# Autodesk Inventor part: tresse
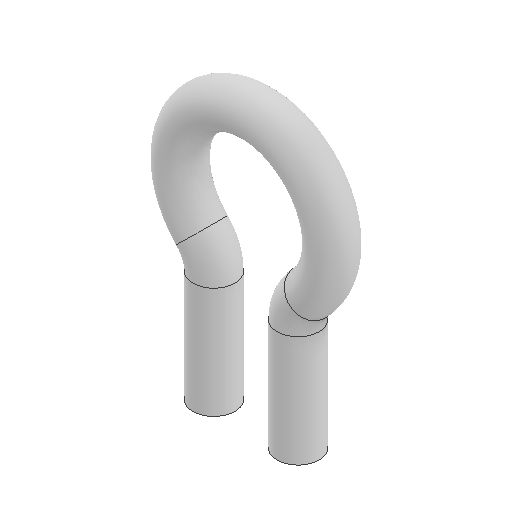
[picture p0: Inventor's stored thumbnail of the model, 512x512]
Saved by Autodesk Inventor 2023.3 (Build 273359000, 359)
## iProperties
Created: 2024-11
Part Number: tresse
Material: Générique
Description: STEP AP203
Document SubType Name: Modeling
Designer: Thier
Density: 1 g/cm^3
Appearance: Par défaut
Sending System: SolidWorks 2017
Preprocessor: SwSTEP 2.0
Title: tresse.STEP
Revision Number: ANY
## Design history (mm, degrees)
feature "Base-Balayage"
node "Solide1"
